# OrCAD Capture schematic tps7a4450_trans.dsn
size A; title: TPS7A44 50-mA, 65-V, Low IQ, Dual Output; rev: 1.0; note: SBVS151E –DECEMBER 2010–REVISED MAY 2015
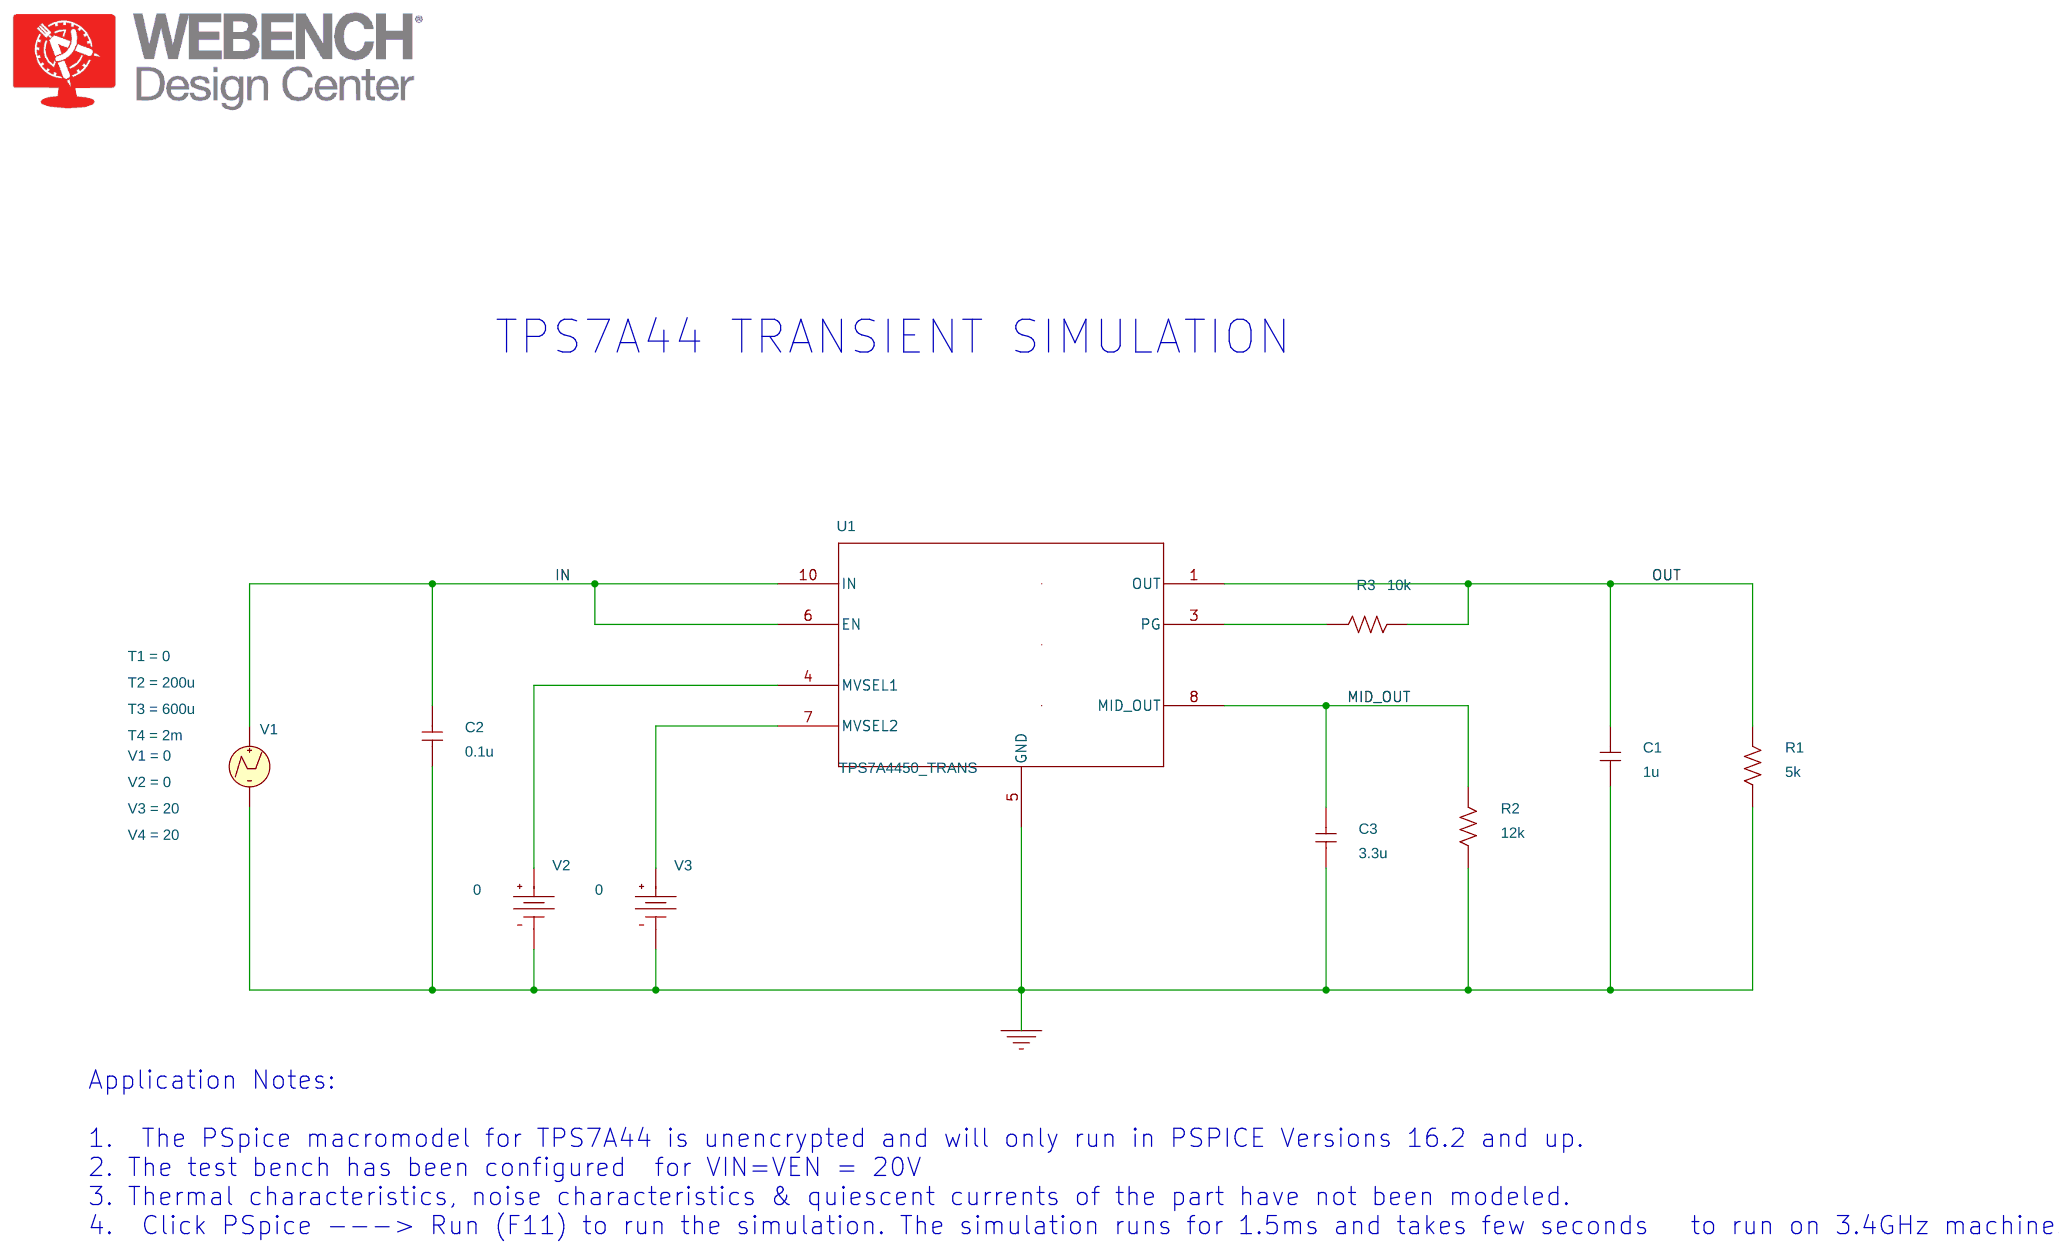
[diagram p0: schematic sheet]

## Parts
C1  1u  [RAD/CK05]
C2  0.1u  [RAD/CK05]
C3  3.3u  [RAD/CK05]
R1  5k  [AX/RC05]
R2  12k  [AX/RC05]
R3  10k  [AXRC05]
U1  TPS7A4450_TRANS  [DBV0005A_N]
V1  VPWL
V2  VDC
V3  VDC

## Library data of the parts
C1-C3 = C
R1-R3 = R
U1 = TPS7A4450_TRANS
V1 = VPWL: PSpiceTemplate: V^@REFDES %+ %- ?DC|DC @DC| ?AC|AC @AC|\n+PWL @T1 @V1 @T2 @V2 #T3/@T3 @V3/ #T4/@T4 @V4/ #T5/@T5 @V5/ #T6/@T6 @V6/ #T7/@T7 @V7/ #T8/@T8 @V8/ #T9/@T9 @V9/ #T10/@T10 @V10/; T1: 0; T2: 200u; T3: 600u; T4: 2m; V1: 0; V2: 0; V3: 20; V4: 20
V2 V3 = VDC: DC: 0

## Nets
0: C1.1 C2.1 C3.1 R1.1 R2.1 U1.5(GND) V1.2(-) V2.1(-) V3.1(-)
IN: C2.2 U1.6(EN) U1.10(IN) V1.1(+)
MID_OUT: C3.2 R2.2 U1.8(MID_OUT)
OUT: C1.2 R1.2 R3.2 U1.1(OUT)
N577142: U1.7(MVSEL2) V3.0(+)
N577149: U1.4(MVSEL1) V2.0(+)
N579801: R3.1 U1.3(PG)

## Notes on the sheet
- TPS7A44 TRANSIENT SIMULATION
- Application Notes:
  1.  The PSpice macromodel for TPS7A44 is unencrypted and will only run in PSPICE Versions 16.2 and up.
  2. The test bench has been configured  for VIN=VEN = 20V
  3. Thermal characteristics, noise characteristics & quiescent currents of the part have not been modeled.
  4.  Click PSpice ---> Run (F11) to run the simulation. The simulation runs for 1.5ms and takes few seconds   to run on 3.4GHz machine.
